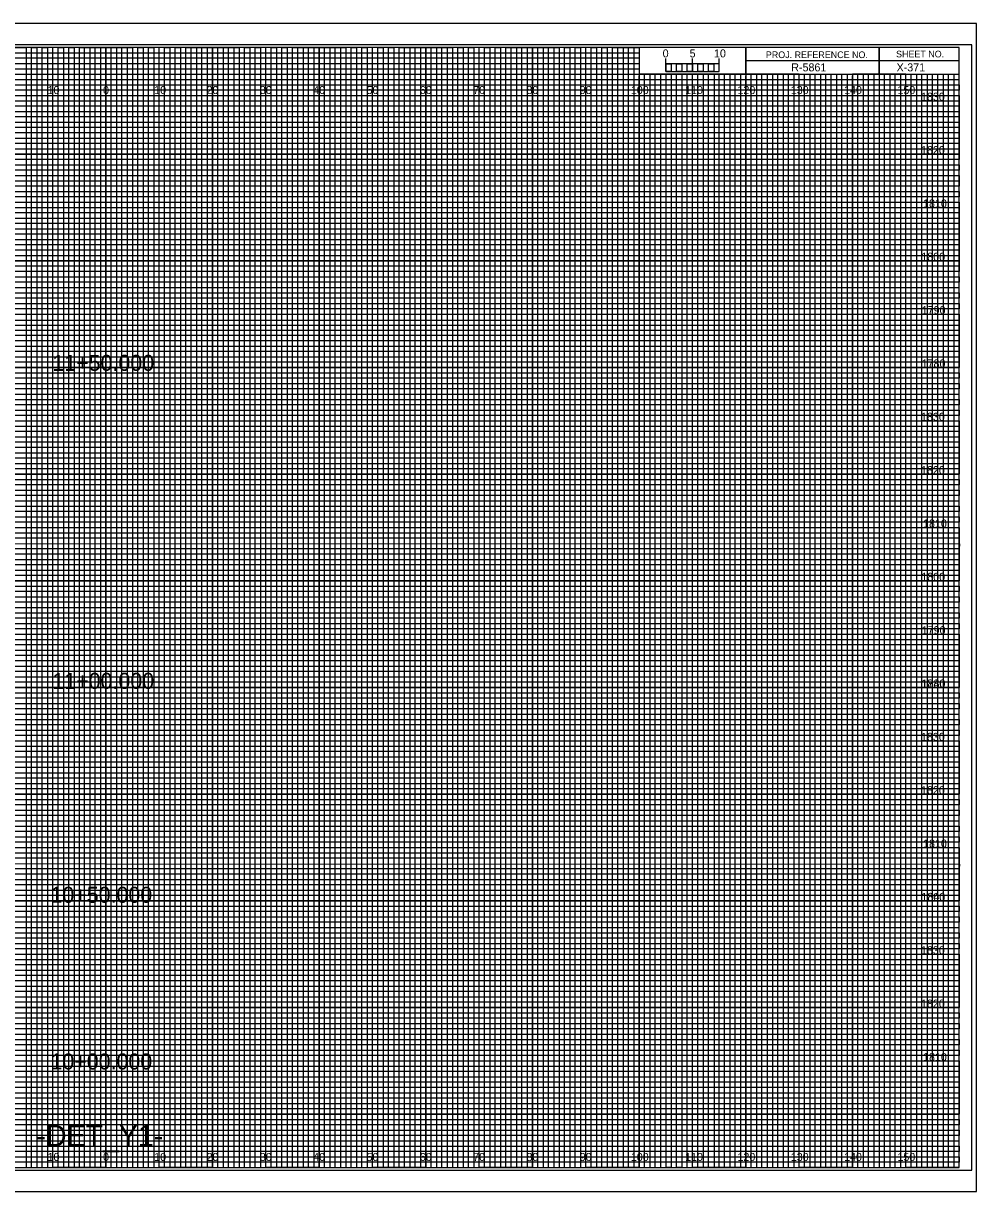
# Model space of a CAD drawing. Extents: x -13 to 323, y -5 to 874.
# Drawn here: x 144.5 to 323.3, y -4.5 to 214.5 of the extents above; entities that cross this region are included whole.
import ezdxf

# ---------------------------------------------------------------- set-up
doc = ezdxf.new("R2010")
doc.units = 0
for name, color, linetype in [('Prop Horizontal Alignment', 7, 'Continuous'), ('Prop XS Alignment Label', 7, 'Continuous'), ('Prop XS Bar Scale Labels', 7, 'Continuous'), ('Prop XS Earthwork Shape', 7, 'Continuous'), ('Prop XS Project Number', 7, 'Continuous'), ('Prop XS Sheet Number', 7, 'Continuous'), ('Raster_Level_0', 7, 'Continuous'), ('Scratch_Level_1', 7, 'Continuous'), ('Scratch_Level_3', 7, 'Continuous'), ('Sheet Cross Section CELL', 7, 'Continuous'), ('Sheet Cross Section Grid Minor 1 CELL', 7, 'Continuous'), ('Sheet Cross Section Grid Minor 2 CELL', 7, 'Continuous'), ('Sheet Cross Section Scale CELL', 7, 'Continuous'), ('Sheet Cutting Line CELL', 7, 'Continuous'), ('Sheet DOT Grid CELL', 7, 'Continuous'), ('Sheet Plot Border Inside CELL', 7, 'Continuous'), ('Sheet Plot Border Outside CELL', 7, 'Continuous')]:
    doc.layers.add(name, color=color, linetype=linetype)

msp = doc.modelspace()

# ---------------------------------------------------------------- linework, layer by layer
at = {"layer": 'Prop XS Earthwork Shape'}
for points in [[(135, 210), (145, 210), (145, 0), (155, 0), (155, 210), (165, 210), (165, 0), (175, 0), (175, 210), (185, 210), (185, 0), (195, 0), (195, 210), (205, 210), (205, 0), (215, 0), (215, 210), (225, 210), (225, 0), (235, 0), (235, 210), (245, 210), (245, 0), (255, 0), (255, 210), (259.93, 210), (260, 210), (260, 205), (264.99, 205), (264.99, 0), (275, 0), (275, 205), (285, 205), (285, 0), (295, 0), (295, 205), (305, 205), (305, 0), (315, 0), (315, 205)], [(0, 205), (275, 205)], [(0, 185), (320, 185), (320, 195), (0, 195)], [(0, 165), (320, 165), (320, 175), (0, 175)], [(0, 145), (320, 145), (320, 155), (0, 155)], [(0, 125), (320, 125), (320, 135), (0, 135)], [(0, 105), (320, 105), (320, 115), (0, 115)], [(0, 85), (320, 85), (320, 95), (0, 95)], [(0, 65), (320, 65), (320, 75), (0, 75)], [(0, 45), (320, 45), (320, 55), (0, 55)], [(0, 25), (320, 25), (320, 35), (0, 35)], [(0, 5), (320, 5), (320, 15), (0, 15)]]:
    msp.add_lwpolyline(points, dxfattribs=at)
at = {"layer": 'Scratch_Level_1'}
for p, q in [((150, 210), (140, 210)), ((150, 0), (150, 210)), ((170, 210), (160, 210)), ((160, 210), (160, 0)), ((170, 0), (170, 210)), ((190, 210), (180, 210)), ((180, 210), (180, 0)), ((190, 0), (190, 210)), ((210, 210), (200, 210)), ((200, 210), (200, 0)), ((210, 0), (210, 210)), ((230, 210), (220, 210)), ((220, 210), (220, 0)), ((230, 0), (230, 210)), ((250, 210), (240, 210)), ((240, 210), (240, 0)), ((250, 0), (250, 210)), ((260, 210), (260, 0)), ((270, 0), (270, 205)), ((290, 205), (280, 205)), ((280, 205), (280, 0)), ((290, 0), (290, 205)), ((310, 205), (300, 205)), ((300, 205), (300, 0)), ((310, 0), (310, 205)), ((160, 0), (150, 0)), ((180, 0), (170, 0)), ((200, 0), (190, 0)), ((220, 0), (210, 0)), ((240, 0), (230, 0)), ((260, 0), (250, 0)), ((280, 0), (270, 0)), ((300, 0), (290, 0)), ((320, 0), (310, 0)), ((320, 0), (320, 0))]:
    msp.add_line(p, q, dxfattribs=at)
for points in [[(0, 200), (320, 200), (320, 190), (0, 190)], [(0, 180), (320, 180), (320, 170), (0, 170)], [(0, 160), (320, 160), (320, 150), (0, 150)], [(0, 140), (320, 140), (320, 130), (0, 130)], [(0, 120), (320, 120), (320, 110), (0, 110)], [(0, 100), (320, 100), (320, 90), (0, 90)], [(0, 80), (320, 80), (320, 70), (0, 70)], [(0, 60), (320, 60), (320, 50), (0, 50)], [(0, 40), (320, 40), (320, 30), (0, 30)], [(0, 20), (320, 20), (320, 10), (0, 10)]]:
    msp.add_lwpolyline(points, dxfattribs=at)
at = {"layer": 'Sheet Cross Section CELL'}
for p, q in [((305, 210), (305, 205)), ((305, 205), (305, 210)), ((280, 207.5), (280, 205)), ((320, 207.49), (280, 207.49)), ((280, 205), (320, 205))]:
    msp.add_line(p, q, dxfattribs=at)
for points in [[(320, 210), (0, 210), (0, 0), (320, 0)], [(280, 210), (260, 210), (260, 205.03), (280, 205.03)], [(320, 210), (280, 210), (280, 205), (320, 205)]]:
    msp.add_lwpolyline(points, close=True, dxfattribs=at)
at = {"layer": 'Sheet Cross Section Grid Minor 1 CELL'}
for p, q in [((0, 209), (260, 209)), ((260, 209), (260, 207.98)), ((260, 207.98), (0, 207.98)), ((0, 207), (260, 207)), ((260, 205.89), (0, 205.89)), ((260, 207), (260, 205.89)), ((0, 204), (320, 204))]:
    msp.add_line(p, q, dxfattribs=at)
for points in [[(0, 203), (270, 203), (320, 203), (320, 202), (0, 202)], [(0, 201), (320, 201), (320, 199), (0, 199)], [(0, 198), (320, 198), (320, 197), (0, 196.98)], [(0, 196), (320, 196), (320, 194), (0, 194)], [(0, 193), (320, 193), (320, 192), (0, 192)], [(0, 191), (320, 191), (320, 189), (0, 189)], [(0, 188), (320, 188), (320, 187), (0, 187)], [(0, 186), (320, 186), (320, 184), (0, 184)], [(0, 183), (320, 183), (320, 182), (0, 182)], [(0, 181), (320, 181), (320, 179), (0, 179)], [(0, 178), (320, 178), (320, 177), (0, 177)], [(0, 176), (320, 176), (320, 173.95), (320, 173), (320, 172), (0, 172)], [(0, 174), (320, 174), (320, 173), (0, 173)], [(0, 171), (320, 171), (320, 169), (0, 169.03)], [(0, 169.03), (320, 169), (320, 168), (0, 168)], [(0, 167), (320, 167), (320, 166), (0, 166)], [(0, 164), (320, 164), (320, 163), (0, 163)], [(0, 162), (320, 162), (320, 161), (0, 161)], [(-0.07, 158.89), (320, 158.89), (320, 157.88), (-0.07, 157.88)], [(0, 157), (320, 157), (320, 156), (0, 156)], [(0, 154), (320, 154), (320, 153), (0, 153)], [(0, 152), (320, 152), (320, 151), (0, 151)], [(0, 149), (320, 149), (320, 148), (0, 148)], [(0, 147), (320, 147), (320, 146), (0, 146)], [(0, 144), (320, 144), (320, 143), (0, 143)], [(0, 142), (320, 142), (320, 141), (0, 141)], [(0, 139), (320, 139), (319.99, 137.98), (0, 138)], [(0, 137), (320, 137), (320, 136), (0, 136)], [(0, 134), (320, 134), (320, 133), (0, 133)], [(0, 132), (320, 132), (320, 131), (0, 131)], [(0, 129), (320, 129), (320, 128), (0, 128)], [(0, 127), (320, 127), (320, 126), (0, 126)], [(0, 124), (320, 124), (320, 123), (0, 123)], [(0, 122), (320, 122), (320, 121), (0, 121)], [(0, 119), (320, 119), (320, 118), (0, 118)], [(0, 116.99), (320.07, 116.91), (320, 116), (0, 116)], [(0, 114), (320, 114), (320, 113), (0, 113)], [(0, 112), (320, 112), (320, 111), (0, 111)], [(0, 109), (320, 109), (320, 108), (0, 108)], [(0, 107), (320, 107), (320, 106), (0, 106)], [(0, 104), (320, 104), (320, 103), (0, 103)], [(0, 102), (320, 102), (320, 101), (0, 101)], [(0, 99), (320, 99), (320, 98), (0, 98)], [(0, 97), (320, 97), (320, 96), (0, 96)], [(0, 94), (320, 94), (320, 93), (0, 93)], [(0, 92), (320, 92), (320, 91), (0, 91)], [(0, 89), (320, 89), (320, 88), (0, 88)], [(0, 87), (320, 87), (320, 86), (0, 86)], [(0, 84), (320, 84), (320, 83), (0, 83)], [(0, 82), (320, 82), (320, 81), (0, 81)], [(0, 79), (320, 79), (319.99, 77.98), (0, 78)], [(0, 77), (320, 77), (320, 76), (0, 76)], [(0, 74), (320, 74), (320, 73), (0, 73)], [(0, 72), (320, 72), (320, 71), (0, 71)], [(0, 69), (320, 69), (320, 68), (0, 68)], [(0, 67), (320, 67), (320, 66), (0, 66)], [(0, 64), (320, 64), (320, 63), (0, 63)], [(0, 62), (320, 62), (320, 61), (0, 61)], [(0, 59), (320, 59), (320, 58), (0, 58)], [(0, 56.99), (320.07, 56.91), (320, 56), (0, 56)], [(0, 54), (320, 54), (320, 53), (0, 53)], [(0, 52), (320, 52), (320, 51), (0, 51)], [(0, 49), (320, 49), (320, 48), (0, 48)], [(0, 47), (320, 47), (320, 46), (0, 46)], [(0, 44), (320, 44), (320, 43), (0, 43)], [(0, 42), (320, 42), (320, 41), (0, 41)], [(0, 39), (320, 39), (320, 38), (0, 38)], [(0, 37), (320, 37), (320, 36), (0, 36)], [(0, 34), (320, 34), (320, 33), (0, 33)], [(0, 32), (320, 32), (320, 31), (0, 31)], [(0, 29), (320, 29), (320, 28), (0, 28)], [(0, 27), (320, 27), (320, 26), (0, 26)], [(0, 24), (320, 24), (320, 23), (0, 23)], [(0, 22), (320, 22), (320, 21), (0, 21)], [(0, 19), (320, 19), (320, 18), (0, 18)], [(0, 17), (320, 17), (320, 16), (0, 16)], [(0, 14), (320, 14), (320, 13), (0, 13)], [(0, 12), (320, 12), (320, 11), (0, 11)], [(0, 9), (320, 9), (320, 8), (0, 8)], [(0, 7), (320, 7), (320, 6), (0, 6)], [(0, 4), (320, 4), (320, 3), (0, 3)], [(0, 2), (320, 2), (320, 1), (0, 1)]]:
    msp.add_lwpolyline(points, dxfattribs=at)
at = {"layer": 'Sheet Cross Section Grid Minor 2 CELL'}
for p, q in [((267, 205), (266.01, 205)), ((266.01, 205), (266.01, 0)), ((267, 0), (267, 205)), ((269, 205), (268, 205)), ((268, 205), (268, 0)), ((269, 0), (269, 205)), ((266.01, 0), (265, 0)), ((268, 0), (267, 0))]:
    msp.add_line(p, q, dxfattribs=at)
for points in [[(145, 0), (146, 0), (146, 210), (147, 210), (147, 0)], [(147, 0), (148, 0), (148, 210), (149, 210), (149, 0)], [(150, 0), (151, 0), (151, 210), (152, 210), (152, 0)], [(152, 0), (153, 0), (153, 210), (154, 210), (154, 0)], [(155, 0), (156, 0), (156, 210), (157, 210), (157, 0)], [(157, 0), (158, 0), (158, 210), (159, 210), (159, 0)], [(160, 0), (161, 0), (161, 210), (162, 210), (162, 0)], [(162, 0), (163, 0), (163, 210), (164, 210), (164, 0)], [(165, 0), (166, 0), (166, 210), (167, 210), (167, 0)], [(167, 0), (168, 0), (168, 210), (169, 210), (169, 0)], [(170, 0), (171, 0), (171, 210), (172, 210), (172, 0)], [(172, 0), (173, 0), (173, 210), (174, 210), (174, 0)], [(175, 0), (176, 0), (176, 210), (177, 210), (177, 0)], [(177, 0), (178, 0), (178, 210), (179, 210), (179, 0)], [(180, 0), (181, 0), (181, 210), (182, 210), (182, 0)], [(182, 0), (183, 0), (183, 210), (184, 210), (184, 0)], [(185, 0), (186, 0), (186, 210), (187, 210), (187, 0)], [(187, 0), (188, 0), (188, 210), (189, 210), (189, 0)], [(190, 0), (191, 0), (191, 210), (192, 210), (192, 0)], [(192, 0), (193, 0), (193, 210), (194, 210), (194, 0)], [(195, 0), (196, 0), (196, 210), (197, 210), (197, 0)], [(197, 0), (198, 0), (198, 210), (199, 210), (199, 0)], [(200, 0), (201, 0), (201, 210), (202, 210), (202, 0)], [(202, 0), (203, 0), (203, 210), (204, 210), (204, 0)], [(205, 0), (206, 0), (206, 210), (207, 210), (207, 0)], [(207, 0), (208, 0), (208, 210), (209, 210), (209, 0)], [(210, 0), (211, 0), (211, 210), (212, 210), (212, 0)], [(212, 0), (213, 0), (213, 210), (214, 210), (214, 0)], [(215, 0), (216, 0), (216, 210), (217, 210), (217, 0)], [(217, 0), (218, 0), (218, 210), (219, 210), (219, 0)], [(220, 0), (221, 0), (221, 210), (222, 210), (222, 0)], [(222, 0), (223, 0), (223, 210), (224, 210), (224, 0)], [(225, 0), (226, 0), (226, 210), (227, 210), (227, 0)], [(227, 0), (228, 0), (228, 210), (229, 210), (229, 0)], [(230, 0), (231, 0), (231, 210), (232, 210), (232, 0)], [(232, 0), (233, 0), (233, 210), (234, 210), (234, 0)], [(235, 0), (236, 0), (236, 210), (237, 210), (237, 0)], [(237, 0), (238, 0), (238, 210), (239, 210), (239, 0)], [(240, 0), (241, 0), (241, 210), (242, 210), (242, 0)], [(242, 0), (243, 0), (243, 210), (244, 210), (244, 0)], [(245, 0), (246, 0), (246, 210), (247, 210), (247, 0)], [(247, 0), (248, 0), (248, 210), (249, 210), (249, 0)], [(250, 0), (251, 0), (251, 210), (252, 210), (252, 0)], [(252, 0), (253, 0), (253, 210), (254, 210), (254, 0)], [(255, 0), (256, 0), (256, 210), (257, 210), (257, 0)], [(257, 0), (258, 0), (258, 210), (259, 210), (259, 0)], [(260, 0), (261, 0), (261, 205), (262.02, 205), (262.02, 0)], [(262, 0), (263, 0), (263, 205), (263.99, 205), (263.99, 0)], [(270, 0), (270.98, 0), (270.98, 205), (272, 205), (272, 0)], [(272, 0), (273, 0), (273, 205), (274.05, 205), (274.05, 0)], [(275, 0), (276, 0), (276, 205), (277, 205), (277, 0)], [(277, 0), (278, 0), (278, 205), (279, 205), (279, 0)], [(280, 0), (281, 0), (281, 205), (282, 205), (282, 0)], [(282, 0), (283, 0), (283, 205), (284, 205), (284, 0)], [(285, 0), (286, 0), (286, 205), (287, 205), (287, 0)], [(287, 0), (288, 0), (288, 205), (289, 205), (289, 0)], [(290, 0), (291, 0), (291, 205), (292, 205), (292, 0)], [(292, 0), (293, 0), (293, 205), (294, 205), (294, 0)], [(295, 0), (296, 0), (296, 205), (297, 205), (297, 0)], [(297, 0), (298, 0), (298, 205), (299, 205), (299, 0)], [(300, 0), (301, 0), (301, 205), (302, 205), (302, 0)], [(302, 0), (303, 0), (303, 205), (304, 205), (304, 0)], [(305, 0), (306, 0), (306, 205), (307, 205), (307, 0)], [(307, 0), (308, 0), (308, 205), (309, 205), (309, 0)], [(310, 0), (311, 0), (311, 205), (312, 205), (312, 0)], [(312, 0), (313, 0), (313, 205), (314, 205), (314, 0)], [(315, 0), (316, 0), (316, 205), (317, 205), (317, 0)], [(317, 0), (318, 0), (318, 205), (319, 205), (319, 0)]]:
    msp.add_lwpolyline(points, dxfattribs=at)
at = {"layer": 'Sheet Cross Section Scale CELL'}
for p, q in [((265, 205.49), (265, 207.9)), ((265, 206.9), (265, 207.9)), ((270, 205.49), (270, 207.9)), ((275, 205.49), (275, 207.9)), ((275, 206.9), (275, 207.9))]:
    msp.add_line(p, q, dxfattribs=at)
for points in [[(275, 206.9), (265, 206.9), (265, 205.49), (275, 205.49)], [(265, 206.9), (266, 206.9), (266, 205.49), (265, 205.49)], [(267, 206.9), (268, 206.9), (268, 205.49), (267, 205.49)], [(269, 206.9), (270, 206.9), (270, 205.49), (269, 205.49)], [(271, 206.9), (272, 206.9), (272, 205.49), (271, 205.49)], [(273, 206.9), (274, 206.9), (274, 205.49), (273, 205.49)]]:
    msp.add_lwpolyline(points, close=True, dxfattribs=at)
at = {"layer": 'Sheet Cutting Line CELL'}
for p, q in [((323.3, 214.5), (-13.4, 214.5)), ((-13.4, -4.5), (323.3, -4.5))]:
    msp.add_line(p, q, dxfattribs=at)
at = {"layer": 'Sheet DOT Grid CELL'}
for p, q in [((150, 0), (150, 210)), ((160, 0), (160, 210)), ((170, 0), (170, 210)), ((180, 0), (180, 210)), ((190, 0), (190, 210)), ((200, 0), (200, 210)), ((210, 0), (210, 210)), ((220, 0), (220, 210)), ((230, 0), (230, 210)), ((240, 0), (240, 210)), ((250, 0), (250, 210)), ((260, 0), (260, 204.69)), ((270, 0), (270, 204.69)), ((280, 0), (280, 204.69)), ((290, 0), (290, 204.69)), ((300, 0), (300, 204.69)), ((310, 0), (310, 204.69)), ((0, 200), (320, 200)), ((0, 190), (320, 190)), ((0, 180), (320, 180)), ((0, 170), (320, 170)), ((0, 160), (320, 160)), ((0, 150), (320, 150)), ((0, 140), (320, 140)), ((0, 130), (320, 130)), ((0, 120), (320, 120)), ((0, 110), (320, 110)), ((0, 100), (320, 100)), ((0, 90), (320, 90)), ((0, 80), (320, 80)), ((0, 70), (320, 70)), ((0, 60), (320, 60)), ((0, 50), (320, 50)), ((0, 40), (320, 40)), ((0, 30), (320, 30)), ((0, 20), (320, 20)), ((0, 10), (320, 10))]:
    msp.add_line(p, q, dxfattribs=at)
at = {"layer": 'Sheet Plot Border Inside CELL'}
msp.add_lwpolyline([(-10.8, -0.5), (322.4, -0.5), (322.4, 210.5), (-10.8, 210.5)], close=True, dxfattribs=at)
at = {"layer": 'Sheet Plot Border Outside CELL'}
msp.add_lwpolyline([(-13.4, -4.5), (323.3, -4.5), (323.3, 214.5), (-13.4, 214.5)], close=True, dxfattribs=at)

# ---------------------------------------------------------------- texts
at = {"layer": 'Prop Horizontal Alignment'}
for s, p in [('11+50.000', (149.95, 149.36)), ('11+00.000', (149.95, 89.75)), ('10+50.000', (149.59, 49.65)), ('10+00.000', (149.59, 18.41))]:
    msp.add_text(s, height=3, dxfattribs=at).set_placement(p)
at = {"layer": 'Prop XS Alignment Label'}
msp.add_text('-DET_Y1-', height=4, dxfattribs=at).set_placement((146.97, 4))
at = {"layer": 'Prop XS Bar Scale Labels'}
for s, p in [('5', (269.47, 208.12)), ('10', (274.04, 208.12))]:
    msp.add_text(s, height=1.5, dxfattribs=at).set_placement(p)
at = {"layer": 'Prop XS Project Number'}
msp.add_text('R-5861', height=1.5, dxfattribs=at).set_placement((288.53, 205.5))
at = {"layer": 'Prop XS Sheet Number'}
msp.add_text('X-371', height=1.5, dxfattribs=at).set_placement((308.28, 205.5))
at = {"layer": 'Raster_Level_0'}
for s, p in [('10', (149.04, 201.25)), ('0', (159.45, 201.25)), ('0', (159.45, 201.25)), ('10', (169.04, 201.25)), ('20', (178.86, 201.25)), ('30', (188.86, 201.25)), ('40', (198.86, 201.25)), ('50', (208.86, 201.25)), ('60', (218.86, 201.25)), ('70', (228.86, 201.25)), ('80', (238.86, 201.25)), ('90', (248.86, 201.25)), ('100', (258.44, 201.25)), ('110', (268.62, 201.25)), ('120', (278.44, 201.25)), ('130', (288.44, 201.25)), ('140', (298.44, 201.25)), ('150', (308.44, 201.25)), ('10', (149.04, 1.25)), ('0', (159.45, 1.25)), ('0', (159.45, 1.25)), ('10', (169.04, 1.25)), ('20', (178.86, 1.25)), ('30', (188.86, 1.25)), ('40', (198.86, 1.25)), ('50', (208.86, 1.25)), ('60', (218.86, 1.25)), ('70', (228.86, 1.25)), ('80', (238.86, 1.25)), ('90', (248.86, 1.25)), ('100', (258.44, 1.25)), ('110', (268.62, 1.25)), ('120', (278.44, 1.25)), ('130', (288.44, 1.25)), ('140', (298.44, 1.25)), ('150', (308.44, 1.25))]:
    msp.add_text(s, height=1.5, dxfattribs=at).set_placement(p)
at = {"layer": 'Scratch_Level_3'}
for s, p in [('1830', (312.86, 200)), ('1820', (312.87, 190)), ('1810', (313.25, 180)), ('1800', (312.92, 170)), ('1790', (313, 160)), ('1780', (312.98, 150)), ('1830', (312.86, 140)), ('1820', (312.87, 130)), ('1810', (313.25, 120)), ('1800', (312.92, 110)), ('1790', (313, 100)), ('1840', (312.95, 90)), ('1780', (312.98, 90)), ('1830', (312.86, 80)), ('1820', (312.87, 70)), ('1810', (313.25, 60)), ('1800', (312.92, 50)), ('1840', (312.95, 50)), ('1830', (312.86, 40)), ('1820', (312.87, 30)), ('1810', (313.25, 20))]:
    msp.add_text(s, height=1.5, dxfattribs=at).set_placement(p)
at = {"layer": 'Sheet Cross Section CELL'}
for s, p in [('PROJ. REFERENCE NO.', (283.77, 207.99)), ('SHEET NO.', (308.19, 208.12))]:
    msp.add_text(s, height=1.25, dxfattribs=at).set_placement(p)
at = {"layer": 'Sheet Cross Section Scale CELL'}
msp.add_text('0', height=1.5, dxfattribs=at).set_placement((264.41, 208.12))

doc.saveas('drawing.dxf')
